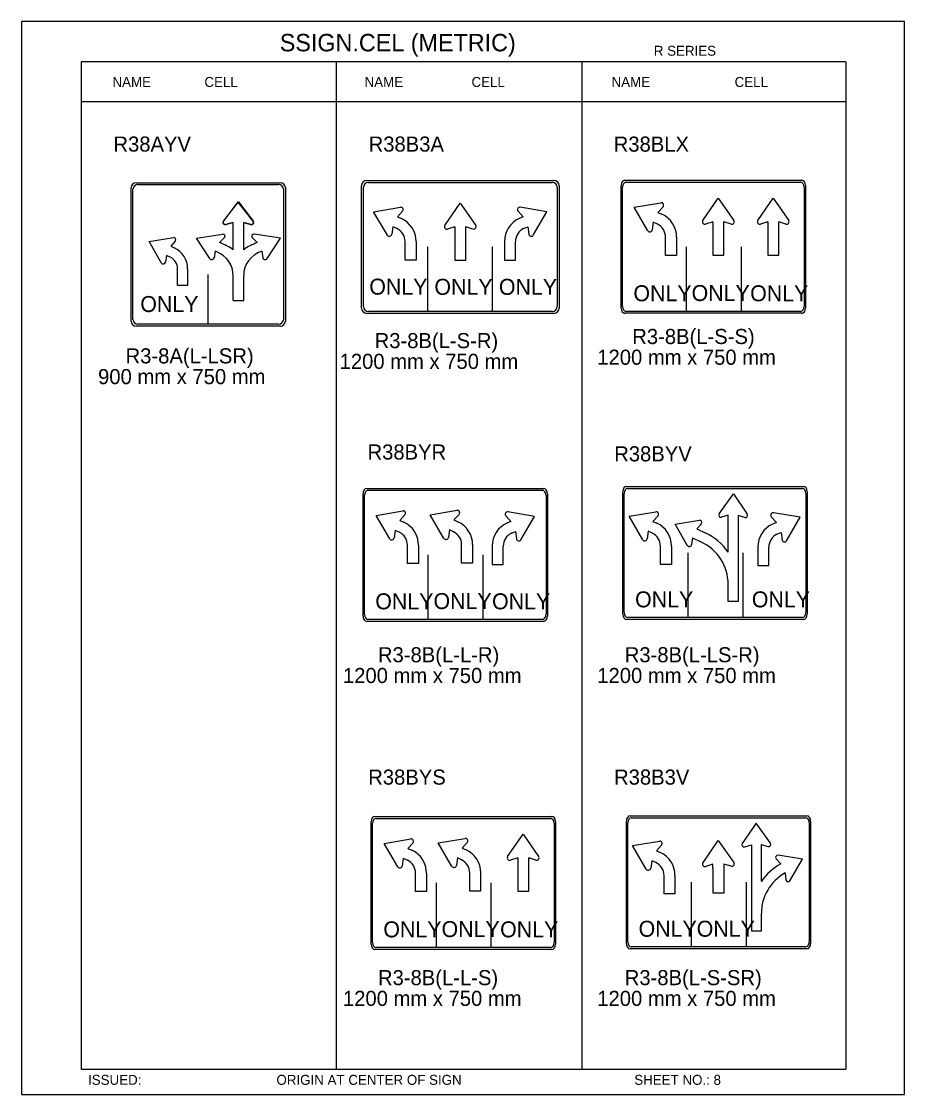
# Model space of a CAD drawing. Extents: x -12 to 6962, y -3756 to 679.
# Drawn here: x 194.1 to 369.4, y -5 to 208 of the extents above; entities that cross this region are included whole.
import ezdxf

# ---------------------------------------------------------------- set-up
doc = ezdxf.new("R2010")
doc.units = 0
for name, color, linetype in [('Level 1', 7, 'Continuous'), ('Level 2', 7, 'Continuous'), ('Level 3', 7, 'Continuous'), ('Level 63', 7, 'Continuous')]:
    doc.layers.add(name, color=color, linetype=linetype)

msp = doc.modelspace()

# ---------------------------------------------------------------- linework, layer by layer
at = {"layer": 'Level 1'}
for p, q in [((357.75, 200), (205.99, 200)), ((205.99, 200), (205.99, 0)), ((256.58, 200), (256.58, 0)), ((305.36, 200), (305.36, 0)), ((357.75, 200), (357.75, 0)), ((357.75, 192.08), (205.99, 192.08)), ((216.25, 148.79), (216.25, 174.78)), ((217.23, 175.66), (245.12, 175.66)), ((246.1, 174.78), (246.1, 148.79)), ((261.98, 151.44), (261.98, 175.12)), ((262.96, 176.1), (299.45, 176.1)), ((300.43, 175.12), (300.43, 151.44)), ((313.41, 151.46), (313.41, 175.13)), ((314.09, 176.11), (348.77, 176.11)), ((349.44, 175.13), (349.44, 151.46)), ((329.34, 168.51), (332.42, 172.96)), ((332.42, 172.96), (335.49, 168.51)), ((340.24, 168.51), (343.32, 172.96)), ((343.32, 172.96), (346.39, 168.51)), ((237.09, 172.23), (234.15, 168.32)), ((234.18, 168.38), (237.22, 172.23)), ((240.13, 168.38), (237.09, 172.23)), ((237.22, 172.23), (240.15, 168.32)), ((264, 170.27), (269.32, 171.17)), ((278.13, 167.54), (281.2, 171.99)), ((281.2, 171.99), (284.28, 167.55)), ((298.41, 170.27), (293.09, 171.17)), ((315.71, 171.15), (321.04, 172.05)), ((318.44, 166.47), (315.71, 171.15)), ((321.46, 171.26), (320.44, 170.14)), ((266.73, 165.6), (264, 170.27)), ((269.74, 170.38), (268.72, 169.26)), ((268.72, 169.26), (269.52, 168.9)), ((292.67, 170.38), (293.69, 169.26)), ((293.69, 169.26), (292.89, 168.9)), ((295.68, 165.6), (298.41, 170.27)), ((320.44, 170.14), (321.23, 169.78)), ((234.69, 167.7), (236.08, 168.11)), ((236.1, 168.13), (234.7, 167.75)), ((236.11, 162.72), (236.11, 168.11)), ((238.21, 168.13), (239.61, 167.75)), ((239.62, 167.7), (238.22, 168.11)), ((238.22, 162.72), (238.22, 168.11)), ((267.8, 167.28), (267.61, 165.79)), ((268.63, 166.91), (267.8, 167.28)), ((280.12, 167.28), (278.67, 166.83)), ((280.12, 167.28), (280.12, 160.67)), ((282.29, 160.67), (282.29, 167.29)), ((283.73, 166.83), (282.29, 167.29)), ((293.78, 166.91), (294.61, 167.28)), ((294.61, 167.28), (294.8, 165.79)), ((319.52, 168.16), (319.32, 166.67)), ((320.34, 167.79), (319.52, 168.16)), ((331.33, 168.25), (329.89, 167.79)), ((331.33, 168.25), (331.33, 161.64)), ((333.51, 161.64), (333.51, 168.25)), ((334.95, 167.8), (333.51, 168.25)), ((342.23, 168.25), (340.78, 167.79)), ((342.23, 168.25), (342.23, 161.64)), ((344.4, 161.64), (344.4, 168.25)), ((345.84, 167.8), (344.4, 168.25)), ((219.43, 164.32), (224.27, 165.14)), ((221.91, 160.07), (219.43, 164.32)), ((224.65, 164.42), (223.73, 163.4)), ((228.83, 165.02), (234, 165.81)), ((231.48, 160.95), (228.83, 165.02)), ((234.41, 165.12), (233.42, 164.15)), ((239.92, 165.12), (240.91, 164.15)), ((245.51, 165.02), (240.33, 165.81)), ((242.85, 160.95), (245.51, 165.02)), ((270.24, 160.67), (270.24, 164.37)), ((272.42, 164.35), (272.42, 160.67)), ((289.99, 164.35), (289.99, 160.67)), ((292.17, 160.67), (292.17, 164.37)), ((321.96, 161.55), (321.96, 165.25)), ((324.13, 165.23), (324.13, 161.55)), ((223.73, 163.4), (224.45, 163.08)), ((232.53, 162.42), (232.34, 161.12)), ((232.86, 162.28), (232.53, 162.42)), ((241.81, 162.42), (242, 161.12)), ((274.8, 150.47), (274.8, 163.28)), ((281.2, 163.28), (281.2, 163.28)), ((287.61, 150.47), (287.61, 163.28)), ((326.09, 150.53), (326.09, 163.32)), ((332.43, 163.06), (332.43, 163.06)), ((336.99, 150.53), (336.99, 163.32)), ((222.89, 161.6), (222.71, 160.25)), ((223.64, 161.26), (222.89, 161.6)), ((231.18, 161.78), (231.18, 161.78)), ((231.18, 161.78), (231.18, 161.78)), ((272.42, 160.67), (270.24, 160.67)), ((280.12, 160.67), (282.29, 160.67)), ((289.99, 160.67), (292.17, 160.67)), ((324.13, 161.55), (321.96, 161.55)), ((331.33, 161.64), (333.51, 161.64)), ((342.23, 161.64), (344.4, 161.64)), ((225.11, 155.59), (225.11, 158.95)), ((227.09, 158.94), (227.09, 155.59)), ((231.18, 147.91), (231.18, 157.83)), ((227.09, 155.59), (225.11, 155.59)), ((236.11, 152.63), (236.11, 157.58)), ((238.22, 152.63), (238.22, 157.58)), ((236.11, 152.63), (238.22, 152.63)), ((299.45, 150.47), (262.96, 150.47)), ((348.77, 150.48), (314.09, 150.48)), ((245.12, 147.91), (217.23, 147.91)), ((314.42, 115.32), (349.1, 115.32)), ((262.18, 90.28), (262.18, 113.96)), ((262.86, 114.94), (297.54, 114.94)), ((298.22, 113.96), (298.22, 90.28)), ((313.75, 90.67), (313.75, 114.34)), ((332.57, 110.25), (335.42, 114.26)), ((335.42, 114.26), (338.16, 110.19)), ((349.78, 114.34), (349.78, 90.67)), ((264.48, 109.97), (269.81, 110.88)), ((275.23, 110.06), (280.56, 110.97)), ((267.22, 105.3), (264.48, 109.97)), ((270.23, 110.09), (269.21, 108.97)), ((269.21, 108.97), (270, 108.61)), ((277.96, 105.39), (275.23, 110.06)), ((280.98, 110.17), (279.96, 109.06)), ((279.96, 109.06), (280.75, 108.69)), ((290.22, 109.88), (291.24, 108.77)), ((291.24, 108.77), (290.44, 108.4)), ((295.97, 109.77), (290.64, 110.68)), ((293.23, 105.1), (295.97, 109.77)), ((314.7, 109.78), (320.03, 110.69)), ((317.43, 105.11), (314.7, 109.78)), ((320.45, 109.89), (319.43, 108.78)), ((319.43, 108.78), (320.22, 108.42)), ((323.83, 108.19), (328.67, 109.01)), ((334.37, 109.99), (333.06, 109.59)), ((334.36, 109.17), (334.37, 109.99)), ((334.36, 102.67), (334.36, 109.17)), ((336.34, 109.18), (336.34, 92.85)), ((337.66, 109.54), (336.35, 109.97)), ((336.35, 109.97), (336.35, 109.18)), ((342.93, 109.69), (343.95, 108.58)), ((348.68, 109.58), (343.35, 110.49)), ((345.95, 104.91), (348.68, 109.58)), ((268.29, 106.99), (268.09, 105.5)), ((269.11, 106.61), (268.29, 106.99)), ((279.04, 107.08), (278.84, 105.58)), ((279.86, 106.7), (279.04, 107.08)), ((291.34, 106.41), (292.16, 106.79)), ((292.16, 106.79), (292.36, 105.29)), ((318.51, 106.8), (318.31, 105.31)), ((319.33, 106.42), (318.51, 106.8)), ((326.31, 103.94), (323.83, 108.19)), ((329.05, 108.29), (328.13, 107.28)), ((328.13, 107.28), (329.79, 106.52)), ((343.95, 108.58), (343.16, 108.21)), ((344.05, 106.22), (344.87, 106.59)), ((344.87, 106.59), (345.07, 105.1)), ((327.29, 105.48), (327.11, 104.12)), ((327.29, 105.48), (328.97, 104.71)), ((270.73, 100.38), (270.73, 104.08)), ((272.91, 104.06), (272.91, 100.38)), ((281.48, 100.46), (281.48, 104.16)), ((283.65, 104.15), (283.65, 100.46)), ((287.54, 103.86), (287.54, 100.18)), ((289.72, 100.18), (289.72, 103.87)), ((320.95, 100.19), (320.95, 103.88)), ((323.12, 103.87), (323.12, 100.19)), ((326.42, 89.74), (326.42, 102.53)), ((332.46, 103.63), (332.46, 103.63)), ((337.32, 89.74), (337.32, 102.53)), ((340.26, 103.67), (340.26, 99.98)), ((342.43, 99.98), (342.43, 103.68)), ((272.91, 100.38), (270.73, 100.38)), ((274.86, 89.36), (274.86, 102.15)), ((281.2, 101.88), (281.2, 101.88)), ((283.65, 100.46), (281.48, 100.46)), ((285.76, 89.36), (285.76, 102.15)), ((287.54, 100.18), (289.72, 100.18)), ((323.12, 100.19), (320.95, 100.19)), ((340.26, 99.98), (342.43, 99.98)), ((334.36, 92.85), (334.36, 96.3)), ((336.34, 92.85), (334.36, 92.85)), ((349.1, 89.69), (314.42, 89.69)), ((297.54, 89.31), (262.86, 89.31)), ((264.46, 49.79), (299.14, 49.79)), ((315.12, 49.92), (349.8, 49.92)), ((263.79, 25.14), (263.79, 48.82)), ((299.82, 48.82), (299.82, 25.14)), ((314.44, 25.26), (314.44, 48.94)), ((339.91, 48.86), (337.17, 44.78)), ((342.76, 44.85), (339.91, 48.86)), ((350.47, 48.94), (350.47, 25.26)), ((266.08, 44.83), (271.41, 45.74)), ((268.82, 40.16), (266.08, 44.83)), ((271.83, 44.94), (270.81, 43.83)), ((276.83, 44.92), (282.16, 45.82)), ((279.56, 40.24), (276.83, 44.92)), ((282.58, 45.03), (281.56, 43.91)), ((290.61, 42.19), (293.69, 46.64)), ((293.69, 46.64), (296.76, 42.2)), ((315.39, 44.38), (320.72, 45.29)), ((329.37, 40.93), (332.39, 45.41)), ((332.39, 45.41), (335.52, 41)), ((270.81, 43.83), (271.61, 43.46)), ((281.56, 43.91), (282.35, 43.55)), ((318.13, 39.71), (315.39, 44.38)), ((321.14, 44.49), (320.12, 43.37)), ((320.12, 43.37), (320.92, 43.01)), ((337.67, 44.14), (338.98, 44.57)), ((338.98, 44.57), (338.98, 43.77)), ((338.99, 43.77), (338.99, 27.45)), ((340.97, 43.76), (340.96, 44.59)), ((340.96, 44.59), (342.27, 44.19)), ((340.97, 37.27), (340.97, 43.76)), ((269.89, 41.85), (269.69, 40.35)), ((270.71, 41.47), (269.89, 41.85)), ((280.64, 41.93), (280.44, 40.44)), ((281.46, 41.56), (280.64, 41.93)), ((292.6, 41.93), (291.16, 41.48)), ((292.6, 41.93), (292.6, 35.32)), ((294.78, 35.32), (294.78, 41.93)), ((296.22, 41.48), (294.78, 41.93)), ((319.2, 41.39), (319.01, 39.9)), ((320.03, 41.02), (319.2, 41.39)), ((331.36, 40.69), (329.92, 40.22)), ((331.36, 39.82), (331.36, 40.69)), ((334.98, 40.28), (333.54, 40.72)), ((333.54, 40.72), (333.54, 39.81)), ((343.9, 41.76), (344.82, 40.75)), ((349.12, 41.66), (344.28, 42.48)), ((346.64, 37.41), (349.12, 41.66)), ((272.33, 35.24), (272.33, 38.93)), ((274.51, 38.92), (274.51, 35.24)), ((283.08, 35.32), (283.08, 39.02)), ((285.25, 39), (285.25, 35.32)), ((321.64, 34.78), (321.64, 38.48)), ((323.82, 38.46), (323.82, 34.78)), ((331.37, 34.91), (331.37, 39.82)), ((333.54, 39.81), (333.54, 34.91)), ((345.66, 38.95), (345.84, 37.59)), ((276.46, 24.21), (276.46, 37)), ((282.81, 36.74), (282.81, 36.74)), ((287.36, 24.21), (287.36, 37)), ((327.12, 24.34), (327.12, 37.13)), ((332.46, 37.1), (332.46, 37.1)), ((338.01, 24.34), (338.01, 37.13)), ((274.51, 35.24), (272.33, 35.24)), ((285.25, 35.32), (283.08, 35.32)), ((292.6, 35.32), (294.78, 35.32)), ((323.82, 34.78), (321.64, 34.78)), ((333.54, 34.91), (331.37, 34.91)), ((340.97, 27.45), (340.97, 30.9)), ((338.99, 27.45), (340.97, 27.45)), ((299.14, 24.16), (264.46, 24.16)), ((349.8, 24.29), (315.12, 24.29)), ((205.99, 0), (357.75, 0))]:
    msp.add_line(p, q, dxfattribs=at)
for centre, radius, start, end in [((262.96, 175.12), 0.977, 90, 180), ((299.45, 175.12), 0.977, 0, 90), ((269.38, 170.7), 0.482, 318.677, 97.1175), ((293.03, 170.7), 0.482, 82.8825, 221.323), ((321.09, 171.58), 0.482, 318.677, 97.1175), ((267.43, 164.36), 5, 359.9807, 65.3304), ((294.98, 164.36), 5, 114.6696, 180.0193), ((319.14, 165.24), 5, 359.9807, 65.3304), ((329.76, 168.26), 0.483, 148.1885, 286.7617), ((335.09, 168.26), 0.482, 253.677, 32.1175), ((340.65, 168.26), 0.483, 148.1885, 286.7617), ((345.98, 168.26), 0.482, 253.677, 32.1175), ((267.42, 164.36), 2.82, 0.0924, 64.7362), ((278.54, 167.29), 0.483, 148.1885, 286.7617), ((283.87, 167.3), 0.482, 253.677, 32.1175), ((294.99, 164.36), 2.82, 115.2638, 179.9076), ((318.84, 166.75), 0.483, 213.1885, 351.7617), ((319.13, 165.23), 2.82, 0.0924, 64.7362), ((224.32, 164.71), 0.438, 318.677, 97.1175), ((267.13, 165.87), 0.483, 213.1885, 351.7617), ((295.28, 165.87), 0.483, 188.2383, 326.8115), ((222.55, 158.95), 4.55, 359.9807, 65.3304), ((222.28, 160.32), 0.439, 213.1885, 351.7617), ((222.54, 158.94), 2.56, 0.0924, 64.7362), ((262.96, 151.44), 0.977, 180, 270), ((299.45, 151.44), 0.977, 270, 0), ((269.86, 110.41), 0.482, 318.677, 97.1175), ((280.61, 110.49), 0.482, 318.677, 97.1175), ((278.66, 104.15), 5, 359.9807, 65.3304), ((290.59, 110.2), 0.482, 82.8825, 221.323), ((320.08, 110.22), 0.482, 318.677, 97.1175), ((328.72, 108.58), 0.438, 318.677, 97.1175), ((332.94, 110.02), 0.439, 147.4967, 286.0699), ((337.79, 109.97), 0.438, 252.9852, 31.4257), ((343.3, 110.01), 0.482, 82.8825, 221.323), ((267.9, 104.06), 2.82, 0.0924, 64.7362), ((267.91, 104.07), 5, 359.9807, 65.3304), ((278.65, 104.15), 2.82, 0.0924, 64.7362), ((292.54, 103.87), 5, 114.6696, 180.0193), ((318.13, 103.88), 5, 359.9807, 65.3304), ((345.25, 103.67), 5, 114.6696, 180.0193), ((267.61, 105.57), 0.483, 213.1885, 351.7617), ((278.36, 105.66), 0.483, 213.1885, 351.7617), ((292.55, 103.86), 2.82, 115.2638, 179.9076), ((292.83, 105.37), 0.483, 188.2383, 326.8115), ((317.83, 105.38), 0.483, 213.1885, 351.7617), ((318.12, 103.87), 2.82, 0.0924, 64.7362), ((325.12, 96.3), 9.25, 0, 65.4104), ((325.12, 96.3), 11.23, 34.5604, 65.4104), ((345.26, 103.67), 2.82, 115.2638, 179.9076), ((345.55, 105.18), 0.483, 188.2383, 326.8115), ((326.68, 104.19), 0.439, 213.1885, 351.7617), ((271.46, 45.26), 0.482, 318.677, 97.1175), ((282.21, 45.35), 0.482, 318.677, 97.1175), ((320.78, 44.81), 0.482, 318.677, 97.1175), ((337.54, 44.56), 0.438, 148.5743, 287.0148), ((342.39, 44.62), 0.439, 253.9301, 32.5033), ((269.51, 38.93), 5, 359.9807, 65.3304), ((280.26, 39.01), 5, 359.9807, 65.3304), ((318.82, 38.47), 5, 359.9807, 65.3304), ((269.51, 38.92), 2.82, 0.0924, 64.7362), ((280.25, 39), 2.82, 0.0924, 64.7362), ((291.02, 41.94), 0.483, 148.1885, 286.7617), ((296.35, 41.95), 0.482, 253.677, 32.1175), ((318.82, 38.47), 2.82, 0.0924, 64.7362), ((329.78, 40.69), 0.482, 148.5743, 287.0148), ((335.11, 40.75), 0.483, 253.9301, 32.5033), ((350.21, 30.9), 11.23, 118.6823, 145.4396), ((344.23, 42.05), 0.438, 82.8825, 221.323), ((269.22, 40.43), 0.483, 213.1885, 351.7617), ((279.96, 40.52), 0.483, 213.1885, 351.7617), ((318.53, 39.98), 0.483, 213.1885, 351.7617), ((350.21, 30.9), 9.25, 119.4871, 180), ((346.27, 37.66), 0.439, 188.2383, 326.8115)]:
    msp.add_arc(centre, radius, start, end, dxfattribs=at)
for centre, major_axis, ratio, start_param, end_param in [((217.23, 174.78), (-0.977, 0), 0.8975, 4.712389, 6.283185), ((245.12, 174.78), (-0.977, 0), 0.8975, 3.141593, 4.712389), ((314.09, 175.13), (0, -0.977), 0.692308, 3.141593, 4.712389), ((348.77, 175.13), (0, 0.977), 0.692308, 4.712389, 6.283185), ((234.58, 168.16), (0.469, 0), 0.8975, 2.574304, 4.992861), ((239.73, 168.16), (0.469, 0), 0.8975, 4.431917, 6.850474), ((234.55, 168.11), (0.468, 0), 0.8975, 2.593111, 5.009353), ((239.76, 168.11), (0.468, 0), 0.8975, 4.415425, 6.831667), ((228.75, 154.22), (12, 0), 0.8975, 0.910414, 1.171257), ((234.05, 165.4), (-0.468, 0), 0.8975, 2.420371, 4.836613), ((245.58, 154.22), (-12, 0), 0.8975, 5.111928, 5.372772), ((240.28, 165.4), (0.468, 0), 0.8975, 1.446573, 3.862814), ((230.55, 157.75), (5.56, 0), 0.8975, 6.249099, 7.424812), ((243.78, 157.75), (-5.56, 0), 0.8975, 5.075391, 6.317271), ((231.87, 161.18), (-0.469, 0), 0.8975, 0.579249, 2.997807), ((242.46, 161.18), (0.469, 0), 0.8975, 3.285378, 5.703936), ((314.09, 151.46), (0, -0.977), 0.692308, 4.712389, 6.283185), ((348.77, 151.46), (0, 0.977), 0.692308, 3.141593, 4.712389), ((217.23, 148.79), (0.977, 0), 0.8975, 3.141593, 4.712389), ((245.12, 148.79), (0.977, 0), 0.8975, 4.712389, 6.283185), ((314.42, 114.34), (0, -0.977), 0.692308, 3.141593, 4.712389), ((349.1, 114.34), (0, 0.977), 0.692308, 4.712389, 6.283185), ((262.86, 113.96), (0, -0.977), 0.692308, 3.141593, 4.712389), ((297.54, 113.96), (0, 0.977), 0.692308, 4.712389, 6.283185), ((262.86, 90.28), (0, -0.977), 0.692308, 4.712389, 6.283185), ((297.54, 90.28), (0, 0.977), 0.692308, 3.141593, 4.712389), ((314.42, 90.67), (0, -0.977), 0.692308, 4.712389, 6.283185), ((349.1, 90.67), (0, 0.977), 0.692308, 3.141593, 4.712389), ((264.46, 48.82), (0, -0.977), 0.692308, 3.141593, 4.712389), ((299.14, 48.82), (0, 0.977), 0.692308, 4.712389, 6.283185), ((315.12, 48.94), (0, -0.977), 0.692308, 3.141593, 4.712389), ((349.8, 48.94), (0, 0.977), 0.692308, 4.712389, 6.283185), ((264.46, 25.14), (0, -0.977), 0.692308, 4.712389, 6.283185), ((299.14, 25.14), (0, 0.977), 0.692308, 3.141593, 4.712389), ((315.12, 25.26), (0, -0.977), 0.692308, 4.712389, 6.283185), ((349.8, 25.26), (0, 0.977), 0.692308, 3.141593, 4.712389)]:
    msp.add_ellipse(centre, major_axis=major_axis, ratio=ratio, start_param=start_param, end_param=end_param, dxfattribs=at)
at = {"layer": 'Level 3'}
for p, q in [((215.86, 148.51), (215.86, 175.06)), ((216.92, 176.01), (245.44, 176.01)), ((246.49, 175.06), (246.49, 148.51)), ((261.59, 151.13), (261.59, 175.43)), ((262.65, 176.49), (299.76, 176.49)), ((300.82, 175.43), (300.82, 151.13)), ((313.14, 151.14), (313.14, 175.44)), ((313.87, 176.5), (348.98, 176.5)), ((349.72, 175.44), (349.72, 151.14)), ((299.76, 150.07), (262.65, 150.07)), ((348.98, 150.09), (313.87, 150.09)), ((245.44, 147.56), (216.92, 147.56)), ((262.64, 115.33), (297.76, 115.33)), ((314.21, 115.71), (349.32, 115.71)), ((261.91, 89.97), (261.91, 114.27)), ((298.49, 114.27), (298.49, 89.97)), ((313.47, 90.35), (313.47, 114.66)), ((350.05, 114.66), (350.05, 90.35)), ((297.76, 88.91), (262.64, 88.91)), ((349.32, 89.3), (314.21, 89.3)), ((263.51, 24.83), (263.51, 49.13)), ((264.25, 50.19), (299.36, 50.19)), ((300.09, 49.13), (300.09, 24.83)), ((314.17, 24.95), (314.17, 49.25)), ((314.9, 50.31), (350.01, 50.31)), ((350.74, 49.25), (350.74, 24.95)), ((299.36, 23.77), (264.25, 23.77)), ((350.01, 23.89), (314.9, 23.89))]:
    msp.add_line(p, q, dxfattribs=at)
for centre, start, end in [((262.65, 175.43), 90, 180), ((299.76, 175.43), 0, 90), ((262.65, 151.13), 180, 270), ((299.76, 151.13), 270, 0)]:
    msp.add_arc(centre, 1.06, start, end, dxfattribs=at)
for centre, major_axis, ratio, start_param, end_param in [((216.92, 175.06), (-1.06, 0), 0.8975, 4.712389, 6.283185), ((245.44, 175.06), (-1.06, 0), 0.8975, 3.141593, 4.712389), ((313.87, 175.44), (0, -1.06), 0.692308, 3.141593, 4.712389), ((348.98, 175.44), (0, 1.06), 0.692308, 4.712389, 6.283185), ((313.87, 151.14), (0, -1.06), 0.692308, 4.712389, 6.283185), ((348.98, 151.14), (0, 1.06), 0.692308, 3.141593, 4.712389), ((216.92, 148.51), (1.06, 0), 0.8975, 3.141593, 4.712389), ((245.44, 148.51), (1.06, 0), 0.8975, 4.712389, 6.283185), ((262.64, 114.27), (0, -1.06), 0.692308, 3.141593, 4.712389), ((297.76, 114.27), (0, 1.06), 0.692308, 4.712389, 6.283185), ((314.21, 114.66), (0, -1.06), 0.692308, 3.141593, 4.712389), ((349.32, 114.66), (0, 1.06), 0.692308, 4.712389, 6.283185), ((262.64, 89.97), (0, -1.06), 0.692308, 4.712389, 6.283185), ((297.76, 89.97), (0, 1.06), 0.692308, 3.141593, 4.712389), ((314.21, 90.35), (0, -1.06), 0.692308, 4.712389, 6.283185), ((349.32, 90.35), (0, 1.06), 0.692308, 3.141593, 4.712389), ((264.25, 49.13), (0, -1.06), 0.692308, 3.141593, 4.712389), ((299.36, 49.13), (0, 1.06), 0.692308, 4.712389, 6.283185), ((314.9, 49.25), (0, -1.06), 0.692308, 3.141593, 4.712389), ((350.01, 49.25), (0, 1.06), 0.692308, 4.712389, 6.283185), ((264.25, 24.83), (0, -1.06), 0.692308, 4.712389, 6.283185), ((299.36, 24.83), (0, 1.06), 0.692308, 3.141593, 4.712389), ((314.9, 24.95), (0, -1.06), 0.692308, 4.712389, 6.283185), ((350.01, 24.95), (0, 1.06), 0.692308, 3.141593, 4.712389)]:
    msp.add_ellipse(centre, major_axis=major_axis, ratio=ratio, start_param=start_param, end_param=end_param, dxfattribs=at)
at = {"layer": 'Level 63'}
msp.add_lwpolyline([(194.12, -5.05), (369.38, -5.05), (369.38, 208.05), (194.12, 208.05)], close=True, dxfattribs=at)

# ---------------------------------------------------------------- texts
at = {"layer": 'Level 1'}
for p in [(263.15, 153.8), (276.07, 153.76), (288.87, 153.76), (315.57, 152.49), (327.12, 152.53), (338.74, 152.48), (217.7, 150.35), (264.34, 91.31), (275.89, 91.36), (287.51, 91.31), (315.9, 91.7), (339.07, 91.7), (265.94, 26.17), (277.49, 26.22), (289.11, 26.17), (316.6, 26.29), (328.13, 26.29)]:
    msp.add_text('ONLY', height=3.17, dxfattribs=at).set_placement(p)
at = {"layer": 'Level 2'}
for s, p in [('R38AYV', (212.37, 182.2)), ('R38B3A', (263.02, 182.2)), ('R38BLX', (311.66, 182.19)), ('R38BYR', (262.8, 121.05)), ('R38BYV', (311.76, 120.69)), ('R38BYS', (262.94, 56.49)), ('R38B3V', (311.73, 56.49))]:
    msp.add_text(s, height=3, dxfattribs=at).set_placement(p)
at = {"layer": 'Level 3'}
for s, height, p in [('SSIGN.CEL (METRIC)', 3.4642, (245.38, 202.11)), ('R SERIES', 1.979, (319.62, 201.24)), ('NAME', 1.98, (212.17, 195.04)), ('CELL', 1.98, (230.43, 195.04)), ('NAME', 1.98, (262.21, 195.04)), ('CELL', 1.98, (283.44, 195.04)), ('NAME', 1.98, (311.23, 195.04)), ('CELL', 1.98, (335.65, 195.04)), ('R3-8B(L-S-S)', 3, (315.34, 143.99)), ('R3-8B(L-S-R)', 3, (264.21, 143.17)), ('R3-8A(L-LSR)', 3, (214.78, 140.14)), ('1200 mm x 750 mm', 3, (308.4, 139.87)), ('1200 mm x 750 mm', 3, (257.26, 139.05)), ('900 mm x 750 mm', 3, (209.32, 136.02)), ('R3-8B(L-L-R)', 3, (264.87, 80.79)), ('R3-8B(L-LS-R)', 3, (313.85, 80.79)), ('1200 mm x 750 mm', 3, (257.92, 76.67)), ('1200 mm x 750 mm', 3, (308.4, 76.67)), ('R3-8B(L-L-S)', 3, (264.87, 16.67)), ('R3-8B(L-S-SR)', 3, (313.85, 16.67)), ('1200 mm x 750 mm', 3, (257.92, 12.55)), ('1200 mm x 750 mm', 3, (308.4, 12.55)), ('ISSUED:', 1.98, (207.33, -3.12)), ('ORIGIN AT CENTER OF SIGN', 1.9795, (244.72, -3.12)), ('SHEET NO.: 8', 1.9795, (315.74, -3.12))]:
    msp.add_text(s, height=height, dxfattribs=at).set_placement(p)

doc.saveas('drawing.dxf')
